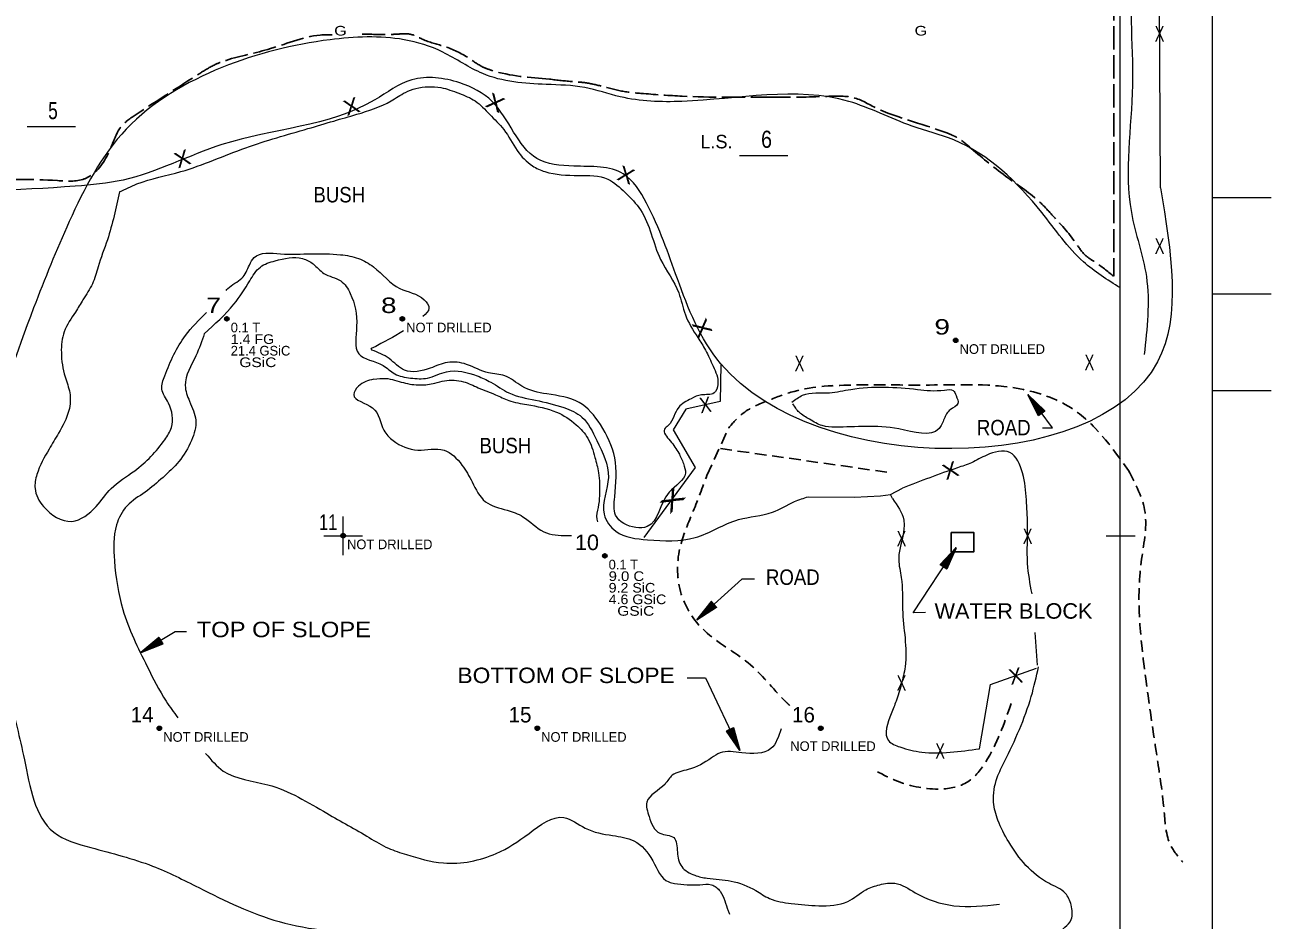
# Model space of a CAD drawing. Extents: x -496 to 480, y -450 to 700.
# Drawn here: x -165 to 480, y -199 to 264 of the extents above; entities that cross this region are included whole.
import ezdxf
from ezdxf.enums import TextEntityAlignment as Align

# ---------------------------------------------------------------- set-up
doc = ezdxf.new("R2010")
doc.units = 0
doc.header["$LTSCALE"] = 2
doc.header["$PDMODE"] = 32
doc.header["$PDSIZE"] = 1
doc.linetypes.add('LONG_DASHED', pattern=[7.5, 6, -1.5])
doc.linetypes.add('MEDIUM_DASHED', pattern=[4.5, 3, -1.5])
for name, color, linetype, lineweight in [('1', 7, 'Continuous', 13), ('2', 7, 'Continuous', 35), ('3', 7, 'Continuous', 13), ('4', 7, 'Continuous', 25)]:
    doc.layers.add(name, color=color, linetype=linetype, lineweight=lineweight)

msp = doc.modelspace()

# ---------------------------------------------------------------- linework, layer by layer
at = {"layer": '1'}
for p, q in [((-163.533, 211.85), (-138.533, 211.85)), ((205.122, 196.887), (230.122, 196.887)), ((480.331, 174.973), (449.983, 174.973)), ((480.331, 124.973), (449.983, 124.973)), ((480.331, 74.973), (449.983, 74.973)), ((-0.017, -10.027), (-0.017, 9.973)), ((-10.017, -0.027), (9.983, -0.027)), ((394.983, -0.027), (409.983, -0.027))]:
    msp.add_line(p, q, dxfattribs=at)
for points in [[(449.983, -450.027), (449.983, 399.973), (449.983, 699.973), (-450.017, 699.973), (-450.017, 49.973), (-450.017, -450.027)], [(402.281, -402.333), (402.281, 402.339), (-402.391, 402.339)]]:
    msp.add_lwpolyline(points, dxfattribs=at)
for p in [(0, 0), (0.001, -0.011)]:
    msp.add_point(p, dxfattribs=at)
at = {"layer": '2', "linetype": 'LONG_DASHED', "lineweight": 25}
msp.add_line((398.852, 398.739), (398.852, 134.415), dxfattribs=at)
at = {"layer": '2'}
for centre in [(-60.213, 112.257), (30.618, 112.257), (317.085, 101.1), (0, 0), (135.423, -10.47), (-95.148, -99.726), (100.488, -99.726), (247.215, -99.726)]:
    msp.add_circle(centre, 1, dxfattribs=at)
at = {"layer": '2', "linetype": 'LONG_DASHED', "lineweight": 25}
for points in [[(-74.266, 239.298), (-66.211, 243.924), (-60.583, 246.086), (-37.636, 252.14), (-10.143, 259.276), (-5.597, 259.276), (-2.783, 259.276)], [(9.773, 259.708), (23.411, 259.492), (29.039, 259.708), (34.235, 259.708), (41.812, 256.681), (52.635, 253.221), (64.758, 247.383), (72.335, 242.626), (76.881, 240.897), (106.755, 236.356)], [(-292.094, 182.712), (-228.927, 183.56), (-186.721, 184.126), (-147.914, 183.843), (-134.034, 184.692), (-129.219, 187.521), (-119.588, 202.517), (-115.056, 211.571), (-107.124, 218.078), (-74.266, 239.298)], [(106.755, 236.356), (118.984, 235.058), (124.3, 234.616), (133.16, 232.846), (144.014, 230.191), (155.533, 228.863), (175.469, 227.536), (219.599, 227.015)], [(219.599, 227.015), (246.416, 227.283), (259.694, 227.432), (262.529, 227.134), (274.613, 222.067), (314.895, 207.464), (318.028, 205.973), (325.04, 200.46)], [(325.04, 200.46), (344.023, 185.301), (360.882, 172.458), (366.883, 166.179), (379.17, 151.622), (384.314, 145.058), (389.171, 141.633), (398.691, 134.376)]]:
    msp.add_spline(points, degree=3, dxfattribs=at)
at = {"layer": '2'}
for points in [[(-60.224, 113.144), (-59.494, 112.74), (-59.342, 111.891), (-60.027, 111.363), (-60.836, 111.594), (-61.123, 112.352), (-60.876, 112.914), (-60.303, 113.082), (-59.629, 112.588), (-59.645, 111.846), (-60.162, 111.588), (-60.685, 111.757), (-60.909, 112.403), (-60.325, 112.869), (-59.887, 112.335), (-59.926, 111.852), (-60.555, 111.987), (-60.409, 112.622), (-60.117, 112.071)], [(30.607, 113.144), (31.337, 112.74), (31.489, 111.891), (30.804, 111.363), (29.995, 111.594), (29.708, 112.352), (29.955, 112.914), (30.528, 113.082), (31.202, 112.588), (31.186, 111.846), (30.669, 111.588), (30.146, 111.757), (29.922, 112.403), (30.506, 112.869), (30.944, 112.335), (30.905, 111.852), (30.276, 111.987), (30.422, 112.622), (30.714, 112.071)], [(317.074, 101.987), (317.804, 101.583), (317.956, 100.734), (317.271, 100.206), (316.462, 100.437), (316.175, 101.195), (316.422, 101.757), (316.995, 101.925), (317.669, 101.431), (317.653, 100.689), (317.136, 100.431), (316.613, 100.6), (316.389, 101.246), (316.973, 101.712), (317.411, 101.178), (317.372, 100.695), (316.743, 100.83), (316.889, 101.465), (317.181, 100.914)], [(-0.011, 0.887), (0.72, 0.483), (0.871, -0.366), (0.186, -0.894), (-0.623, -0.663), (-0.909, 0.095), (-0.662, 0.657), (-0.089, 0.825), (0.585, 0.331), (0.568, -0.411), (0.051, -0.669), (-0.471, -0.5), (-0.696, 0.146), (-0.112, 0.612), (0.326, 0.078), (0.287, -0.405), (-0.342, -0.27), (-0.196, 0.365), (0.096, -0.186)], [(135.412, -9.583), (136.142, -9.987), (136.294, -10.836), (135.609, -11.364), (134.8, -11.133), (134.513, -10.375), (134.76, -9.813), (135.333, -9.645), (136.007, -10.139), (135.991, -10.881), (135.474, -11.139), (134.951, -10.97), (134.727, -10.324), (135.311, -9.858), (135.749, -10.392), (135.71, -10.875), (135.081, -10.74), (135.227, -10.105), (135.519, -10.656)], [(-95.159, -98.839), (-94.429, -99.243), (-94.277, -100.092), (-94.962, -100.62), (-95.771, -100.389), (-96.058, -99.631), (-95.811, -99.069), (-95.238, -98.901), (-94.564, -99.395), (-94.58, -100.137), (-95.097, -100.395), (-95.62, -100.226), (-95.844, -99.58), (-95.26, -99.114), (-94.822, -99.648), (-94.861, -100.131), (-95.49, -99.996), (-95.344, -99.361), (-95.052, -99.912)], [(100.477, -98.839), (101.207, -99.243), (101.359, -100.092), (100.674, -100.62), (99.865, -100.389), (99.578, -99.631), (99.825, -99.069), (100.398, -98.901), (101.072, -99.395), (101.056, -100.137), (100.539, -100.395), (100.016, -100.226), (99.792, -99.58), (100.376, -99.114), (100.814, -99.648), (100.775, -100.131), (100.146, -99.996), (100.292, -99.361), (100.584, -99.912)], [(247.204, -98.839), (247.934, -99.243), (248.086, -100.092), (247.401, -100.62), (246.592, -100.389), (246.305, -99.631), (246.552, -99.069), (247.125, -98.901), (247.799, -99.395), (247.783, -100.137), (247.266, -100.395), (246.743, -100.226), (246.519, -99.58), (247.103, -99.114), (247.541, -99.648), (247.502, -100.131), (246.873, -99.996), (247.019, -99.361), (247.311, -99.912)]]:
    msp.add_spline(points, degree=3, dxfattribs=at)
at = {"layer": '3'}
for p, q in [((423.111, 180.13), (421.865, 389.84)), ((16.912, 97.981), (14.565, 96.92)), ((14.898, 96.102), (14.565, 96.92)), ((359.343, -67.011), (358.14, -50.222))]:
    msp.add_line(p, q, dxfattribs=at)
at = {"layer": '3', "linetype": 'MEDIUM_DASHED', "lineweight": 25}
for p, q in [((188.293, 31.175), (199.59, 55.839)), ((195.292, 45.086), (283.839, 32.529))]:
    msp.add_line(p, q, dxfattribs=at)
at = {"layer": '3'}
for points in [[(31.212, 106.099), (25.451, 102.605), (19.484, 99.42), (16.912, 97.981)], [(195.456, 88.647), (195.212, 69.401), (177.407, 65.503), (170.822, 54.783), (182.285, 35.293), (155.699, -1.007)], [(240.81, 20.183), (264.755, 19.952), (278.099, 20.557), (283.304, 21.24)], [(284.272, 19.272), (283.304, 21.24), (289.557, 24.551)], [(329.377, -110.288), (335.037, -77.01), (358.914, -68.662)]]:
    msp.add_lwpolyline(points, dxfattribs=at)
at = {"layer": '3', "lineweight": 25}
msp.add_lwpolyline([(314.741, 1.694), (326.381, 1.694), (326.381, -8.442), (314.741, -8.442)], close=True, dxfattribs=at)
at = {"layer": '3'}
for points in [[(419.648, 380.431), (413.553, 376.556), (407.457, 353.863), (407.457, 336.705), (411.89, 329.509), (413.553, 314.565), (410.228, 298.514), (408.565, 233.202), (408.011, 167.337), (415.769, 134.128), (414.661, 93.723)], [(402.334, 128.248), (383.156, 141.817), (361.58, 167.359), (316.03, 204.874), (294.455, 212.058), (261.691, 224.828), (175.387, 224.828), (143.423, 227.223), (125.043, 232.012), (105.066, 233.608), (72.302, 239.196), (51.525, 250.37), (31.548, 256.756), (-6.81, 256.756), (-62.747, 242.389), (-112.292, 210.461), (-141.859, 162.57), (-160.239, 117.872), (-180.217, 46.833), (-177.819, -26.6), (-172.225, -83.271), (-165.033, -115.996), (-149.85, -153.511), (-130.672, -161.493), (-98.707, -171.071), (-74.734, -182.245), (-33.18, -199.806), (16.364, -206.191), (58.717, -207.787), (95.476, -213.375), (128.24, -226.944), (149.017, -239.715), (176.985, -270.046), (196.164, -292.395), (211.347, -300.377), (239.316, -307.56), (295.735, -304.937)], [(423.111, 180.13), (421.513, 89.935), (195.365, 89.137), (172.99, 133.037), (157.008, 172.148), (145.021, 187.314), (119.45, 191.305), (100.271, 195.296), (77.097, 224.828), (60.315, 234.407), (35.543, 236.003), (16.364, 225.627), (-62.747, 202.479), (-113.89, 184.121), (-138.663, 180.928), (-318.462, 179.332)], [(-115.725, 178.018), (-106.787, 182.072), (-84.032, 188.495), (-50.396, 200.847), (-18.243, 210.729), (-4.888, 214.682), (6.984, 218.14), (24.792, 225.057), (32.211, 229.504), (37.653, 231.48), (50.514, 231.974), (59.912, 229.01), (68.321, 225.057), (75.741, 218.14), (83.161, 210.235), (90.086, 199.365), (98, 191.46), (104.431, 188.495), (121.744, 186.519), (137.078, 184.543), (145.982, 177.626), (153.896, 168.732), (164.284, 143.04), (173.682, 125.747), (177.145, 114.383), (183.576, 102.525), (187.533, 96.102), (191.49, 87.703), (193.963, 78.315), (191.985, 73.868), (185.554, 72.88), (180.113, 70.904), (173.682, 66.457), (168.241, 57.07), (166.263, 55.093), (169.231, 49.164), (173.682, 42.741), (176.156, 37.306), (177.145, 32.366), (168.736, 22.484), (157.359, 4.697), (151.423, 4.203), (141.035, 10.626), (140.541, 20.013), (140.541, 40.271), (133.121, 57.564), (122.238, 68.928), (105.42, 73.374), (92.559, 77.327), (83.655, 82.762), (75.246, 84.244), (63.869, 88.691), (53.976, 89.679), (45.072, 86.714), (31.717, 85.726), (23.802, 91.655), (14.898, 96.102)], [(-115.725, 178.018), (-122.053, 153.224), (-126.92, 139.125), (-129.84, 130.374), (-134.708, 122.109), (-138.601, 115.789), (-144.442, 105.58), (-145.902, 94.884), (-143.955, 82.244), (-141.522, 73.979), (-142.008, 64.742), (-147.362, 53.075), (-152.23, 44.81), (-158.557, 31.684), (-159.53, 24.391), (-155.15, 15.154), (-140.548, 7.376), (-127.893, 15.154), (-120.106, 24.391), (-107.938, 33.628), (-92.363, 49.671), (-88.956, 55.992), (-90.416, 68.632), (-93.823, 75.924), (-92.363, 82.73), (-81.655, 103.635), (-70.752, 115.568)], [(-71.904, 104.574), (-56.57, 119.89), (-48.356, 131.924), (-42.88, 139.035), (-35.213, 142.316), (-20.975, 143.41), (-15.498, 140.675), (-10.022, 135.753), (-1.26, 131.924), (3.669, 125.36), (6.954, 108.403), (8.05, 94.181), (20.645, 88.164), (26.669, 83.788), (34.883, 81.601), (43.645, 81.601), (53.502, 84.882), (69.384, 82.694), (76.503, 79.413), (85.812, 73.943), (99.503, 70.114), (114.289, 66.285), (123.598, 61.362), (131.265, 49.328), (137.289, 30.183), (135.099, 11.039), (141.122, 2.287), (157.551, -2.089), (182.194, -0.995), (204.647, 8.304), (222.171, 12.133), (233.671, 17.603), (240.81, 20.183)], [(-60.631, 126.953), (-59.752, 127.943), (-52.451, 133.291), (-48.557, 140.097), (-46.124, 143.987), (-32.496, 145.931), (-16.434, 145.931), (-1.345, 145.445), (7.902, 143.5), (15.69, 139.125), (29.318, 127.943), (41.973, 122.109), (44.407, 117.734), (41.226, 113.523)], [(-71.904, 104.574), (-76.285, 93.087), (-81.761, 77.772), (-79.57, 69.567), (-76.285, 59.721), (-78.475, 49.328), (-85.047, 38.388), (-93.261, 30.183), (-102.571, 22.526), (-111.88, 15.415), (-117.356, 5.569), (-118.452, -13.029), (-114.071, -38.19), (-101.475, -67.728), (-91.618, -85.779), (-85.634, -94.242)], [(15.787, 80.98), (7.902, 77.383), (5.469, 73.007), (15.203, 66.201), (21.044, 54.533), (25.911, 49.185), (38.566, 44.324), (52.194, 44.324), (61.442, 36.545), (66.796, 27.794), (73.61, 17.585), (84.805, 13.209), (93.079, 9.806), (103.787, 2.028), (115.955, 0.083), (118.246, 0.098)], [(15.787, 80.98), (22.007, 81.398), (31.21, 79.221), (39.928, 78.011), (47.436, 78.979), (52.521, 80.188), (62.208, 79.704), (69.958, 76.56), (78.918, 72.931), (85.699, 70.029), (95.144, 67.852), (110.401, 63.981), (120.572, 57.45), (126.627, 50.435), (130.259, 40.517), (132.197, 32.535), (132.681, 26.971), (132.681, 20.682), (131.955, 14.635), (131.228, 8.587), (131.64, 7.197)], [(232.236, 69.041), (237.802, 72.684), (251.813, 74.026), (262.753, 75.751), (297.301, 75.751), (311.312, 75.368), (315.727, 75.176), (317.262, 72.492), (318.222, 68.466), (314.191, 65.207), (311.12, 60.414), (308.433, 55.43), (287.704, 55.238), (254.692, 56.197), (247.974, 56.963), (241.449, 60.223), (236.075, 63.865), (232.812, 68.274)], [(356.579, -30.048), (354.301, -14.383), (354.301, 6.074), (353.64, 18.612), (351.658, 32.469), (345.052, 43.027), (333.16, 41.708), (325.232, 37.748), (317.965, 35.109), (289.557, 24.551)], [(284.272, 19.272), (290.218, 8.053), (287.575, -12.403), (288.896, -21.641), (289.557, -38.138), (290.878, -67.833), (288.896, -77.072), (286.254, -85.65), (283.611, -92.249), (282.29, -106.107), (288.236, -109.406), (299.467, -112.046), (329.377, -110.288)], [(332.652, -234.524), (333.309, -234.347), (343.071, -229.097), (357.338, -217.846), (368.977, -206.221), (376.861, -198.72), (376.861, -191.22), (373.858, -185.22), (365.222, -179.97), (344.573, -158.594), (338.941, -147.344), (336.688, -137.968), (338.566, -125.218), (342.32, -116.968), (356.212, -83.216), (359.966, -67.841)], [(226.682, -100.092), (221.426, -110.217), (206.408, -112.467), (195.144, -112.467), (190.639, -115.092), (178.625, -121.093), (170.365, -124.093), (166.61, -128.593), (157.224, -137.968), (158.35, -145.469), (163.982, -154.094), (171.116, -156.344), (172.993, -163.844), (175.246, -171.344), (182.004, -175.845), (188.386, -177.345), (200.776, -178.845), (213.541, -183.72), (220.675, -187.845), (231.938, -190.47), (246.205, -191.595), (261.223, -189.345), (270.609, -183.345), (277.743, -180.72), (285.627, -179.97), (296.14, -184.845), (316.039, -191.595), (339.692, -190.845)], [(-71.2, -112.726), (-62.046, -121.88), (-39.046, -128.991), (-8.379, -143.76), (13.526, -156.34), (23.383, -161.81), (32.693, -165.092), (51.86, -169.468), (79.241, -164.545), (96.217, -154.152), (114.289, -145.948), (125.241, -151.417), (139.48, -155.246), (150.432, -157.981), (160.289, -168.374), (168.504, -179.314), (171.523, -180.091)], [(171.523, -180.091), (184.632, -180.72), (190.639, -180.72), (195.144, -184.095), (199.274, -194.22), (200.015, -195.905)]]:
    msp.add_spline(points, degree=3, dxfattribs=at)
at = {"layer": '3', "linetype": 'MEDIUM_DASHED', "lineweight": 25}
for points in [[(199.59, 55.839), (206.315, 62.824), (220.189, 70.083), (233.402, 74.702), (265.113, 78.001), (306.073, 78.001), (350.337, 76.022), (376.763, 66.123), (406.492, 33.789)], [(406.492, 33.789), (415.08, 12.013), (413.098, -13.723), (415.08, -71.133), (421.687, -117.325), (424.99, -143.06), (428.293, -160.217), (434.652, -169.062)], [(231.158, -87.942), (228.777, -85.65), (209.618, -65.854), (187.156, -49.356), (174.604, -28.9), (174.604, -5.144), (181.21, 12.673), (188.293, 31.175)], [(345.712, -86.97), (332.499, -117.325), (322.589, -127.883), (308.055, -131.182), (285.593, -126.563), (274.179, -121.021)]]:
    msp.add_spline(points, degree=3, dxfattribs=at)
at = {"layer": '4', "lineweight": 13}
for points in [[(361.925, 55.866), (367.213, 55.866), (354.434, 73.032)], [(301.427, -39.716), (295.078, -39.908), (317.394, -6.088)], [(212.983, -22.481), (206.373, -22.481), (183.018, -43.608)], [(-81.03, -49.847), (-86.941, -49.847), (-104.677, -60.583)], [(178.082, -73.54), (187.53, -73.54), (205.377, -111.288)]]:
    msp.add_lwpolyline(points, dxfattribs=at)
at = {"layer": '4'}
for points in [[(354.434, 73.032), (359.996, 62.212), (363.204, 64.6)], [(317.394, -6.088), (309.116, -15.003), (312.454, -17.206)], [(183.018, -43.608), (193.259, -37.041), (190.575, -34.074)], [(-104.677, -60.583), (-93.375, -56.08), (-95.447, -52.658)], [(205.377, -111.288), (202.056, -99.585), (198.44, -101.295)]]:
    msp.add_lwpolyline(points, close=True, dxfattribs=at)
for points in [[(360.032, 62.361), (354.776, 72.571), (362.975, 64.633), (360.145, 62.5), (355.216, 71.98), (362.722, 64.687), (360.164, 62.727), (355.681, 71.356), (362.431, 64.712), (360.259, 62.96), (356.192, 70.634), (362.132, 64.788), (360.304, 63.265), (356.807, 69.769), (361.808, 64.789), (360.383, 63.592), (357.474, 68.839), (361.381, 64.82), (360.418, 63.942), (358.171, 67.793), (360.966, 64.942), (360.432, 64.356), (359.079, 66.609), (360.441, 65.036)], [(309.269, -14.986), (317.078, -6.567), (312.407, -16.98), (309.438, -15.045), (316.672, -7.182), (312.371, -16.723), (309.658, -14.985), (316.243, -7.831), (312.296, -16.441), (309.909, -14.996), (315.739, -8.558), (312.266, -16.134), (310.211, -14.934), (315.135, -9.431), (312.156, -15.829), (310.546, -14.897), (314.487, -10.374), (312.04, -15.416), (310.886, -14.81), (313.742, -11.387), (312.013, -14.986), (311.281, -14.683), (312.938, -12.643), (311.922, -14.459)], [(193.107, -37.019), (183.444, -43.223), (190.565, -34.305), (192.957, -36.919), (183.99, -42.729), (190.535, -34.563), (192.73, -36.922), (184.567, -42.207), (190.537, -34.855), (192.489, -36.85), (185.237, -41.629), (190.491, -35.159), (192.181, -36.834), (186.04, -40.935), (190.521, -35.482), (191.847, -36.787), (186.902, -40.183), (190.53, -35.91), (191.497, -36.785), (187.877, -39.388), (190.449, -36.334), (191.082, -36.81), (188.969, -38.372), (190.405, -36.867)], [(-93.52, -56.029), (-104.185, -60.287), (-95.501, -52.883), (-93.648, -55.903), (-103.555, -59.905), (-95.579, -53.13), (-93.872, -55.863), (-102.889, -59.502), (-95.632, -53.417), (-94.095, -55.746), (-102.122, -59.062), (-95.736, -53.707), (-94.394, -55.673), (-101.202, -58.533), (-95.768, -54.03), (-94.713, -55.562), (-100.213, -57.958), (-95.839, -54.452), (-95.057, -55.495), (-99.105, -57.363), (-96, -54.853), (-95.469, -55.441), (-97.84, -56.573), (-96.144, -55.367)], [(201.991, -99.724), (205.132, -110.769), (198.658, -101.372), (201.853, -99.838), (204.817, -110.103), (198.896, -101.474), (201.79, -100.057), (204.485, -109.4), (199.176, -101.557), (201.65, -100.267), (204.126, -108.591), (199.454, -101.69), (201.547, -100.557), (203.693, -107.622), (199.772, -101.755), (201.404, -100.862), (203.223, -106.579), (200.184, -101.869), (201.302, -101.198), (202.745, -105.416), (200.566, -102.07), (201.206, -101.602), (202.089, -104.076), (201.063, -102.266)]]:
    msp.add_lwpolyline(points, dxfattribs=at)

# ---------------------------------------------------------------- texts
at = {"layer": '1'}
for s, width, p in [('5', 0.75, (-150.235, 215.639)), ('6', 0.85, (219.146, 200.791))]:
    msp.add_text(s, height=8.89, dxfattribs=dict(at, width=width)).set_placement(p, align=Align.CENTER)
msp.add_text('L.S.', height=7, dxfattribs=at).set_placement((193.216, 200.511), align=Align.CENTER)
at = {"layer": '2'}
for s, width, p in [('  G        ', 1.25, (-9.304, 258.926)), ('  G        ', 1.25, (291.137, 258.926)), ('1.4 FG     ', 1.1, (-58.213, 99.257)), ('  GSiC     ', 1.2, (-58.213, 87.257)), ('9.0 C      ', 1.15, (137.423, -23.47)), ('9.2 SiC    ', 1.1, (137.423, -29.47)), ('4.6 GSiC   ', 1.1, (137.423, -35.47)), ('  GSiC     ', 1.2, (137.423, -41.47))]:
    msp.add_text(s, height=5, dxfattribs=dict(at, width=width)).set_placement(p)
for s, width, p in [('  7', 1.3, (-63.214, 115.257)), ('  8', 1.35, (27.617, 115.257)), ('  9', 1.35, (314.084, 104.1)), (' 11', 0.8, (-3, 3)), (' 10', 1.05, (132.422, -7.47))]:
    msp.add_text(s, height=8, dxfattribs=dict(at, width=width)).set_placement(p, align=Align.RIGHT)
for s, p in [('0.1 T      ', (-58.213, 105.257)), ('NOT DRILLED', (32.618, 105.257)), ('21.4 GSiC  ', (-58.213, 93.257)), ('NOT DRILLED', (319.085, 94.1)), ('NOT DRILLED', (2, -7)), ('0.1 T      ', (137.423, -17.47)), ('NOT DRILLED', (-93.148, -106.726)), ('NOT DRILLED', (102.488, -106.726)), ('NOT DRILLED', (231.448, -111.487))]:
    msp.add_text(s, height=5, dxfattribs=at).set_placement(p)
for s, p in [(' 14', (-98.149, -96.726)), (' 15', (97.487, -96.726)), (' 16', (244.214, -96.726))]:
    msp.add_text(s, height=8, dxfattribs=at).set_placement(p, align=Align.RIGHT)
at = {"layer": '3', "width": 0.7}
for p in [(422.6, 255.813), (422.615, 145.892), (236.193, 85.105), (386.286, 85.676), (289.023, -5.551), (354.309, -4.305), (289.025, -80.338), (309.024, -115.479)]:
    msp.add_text('X', height=8, dxfattribs=at).set_placement(p, align=Align.CENTER)
at = {"layer": '3'}
for rotation, width, p in [(18.477, 1.1, (5.572, 218.443)), (334.54, 1.25, (77.071, 220.513)), (19.77, 1.1, (-81.914, 191.417)), (339.077, 1.15, (144.996, 183.013)), (296.452, 1.25, (182.297, 105.806)), (8.266, 0.85, (188.038, 63.779)), (19.596, 1.1, (315.681, 30.024)), (46.299, 1.8, (173.354, 15.449)), (11.816, 0.95, (348.921, -76.559))]:
    msp.add_text('X', height=8, rotation=rotation, dxfattribs=dict(at, width=width)).set_placement(p, align=Align.CENTER)
at = {"layer": '4'}
for s, width, p in [('BUSH', 0.9, (-2.027, 172.519)), ('ROAD', 0.9, (341.948, 51.953)), ('BUSH', 0.9, (83.946, 42.644)), ('ROAD', 0.9, (232.763, -25.492)), ('WATER BLOCK', 1.05, (347.003, -42.993)), ('TOP OF SLOPE', 1.15, (-30.715, -52.57)), ('BOTTOM OF SLOPE', 1.1, (115.396, -76.324))]:
    msp.add_text(s, height=8, dxfattribs=dict(at, width=width)).set_placement(p, align=Align.CENTER)

doc.saveas('drawing.dxf')
